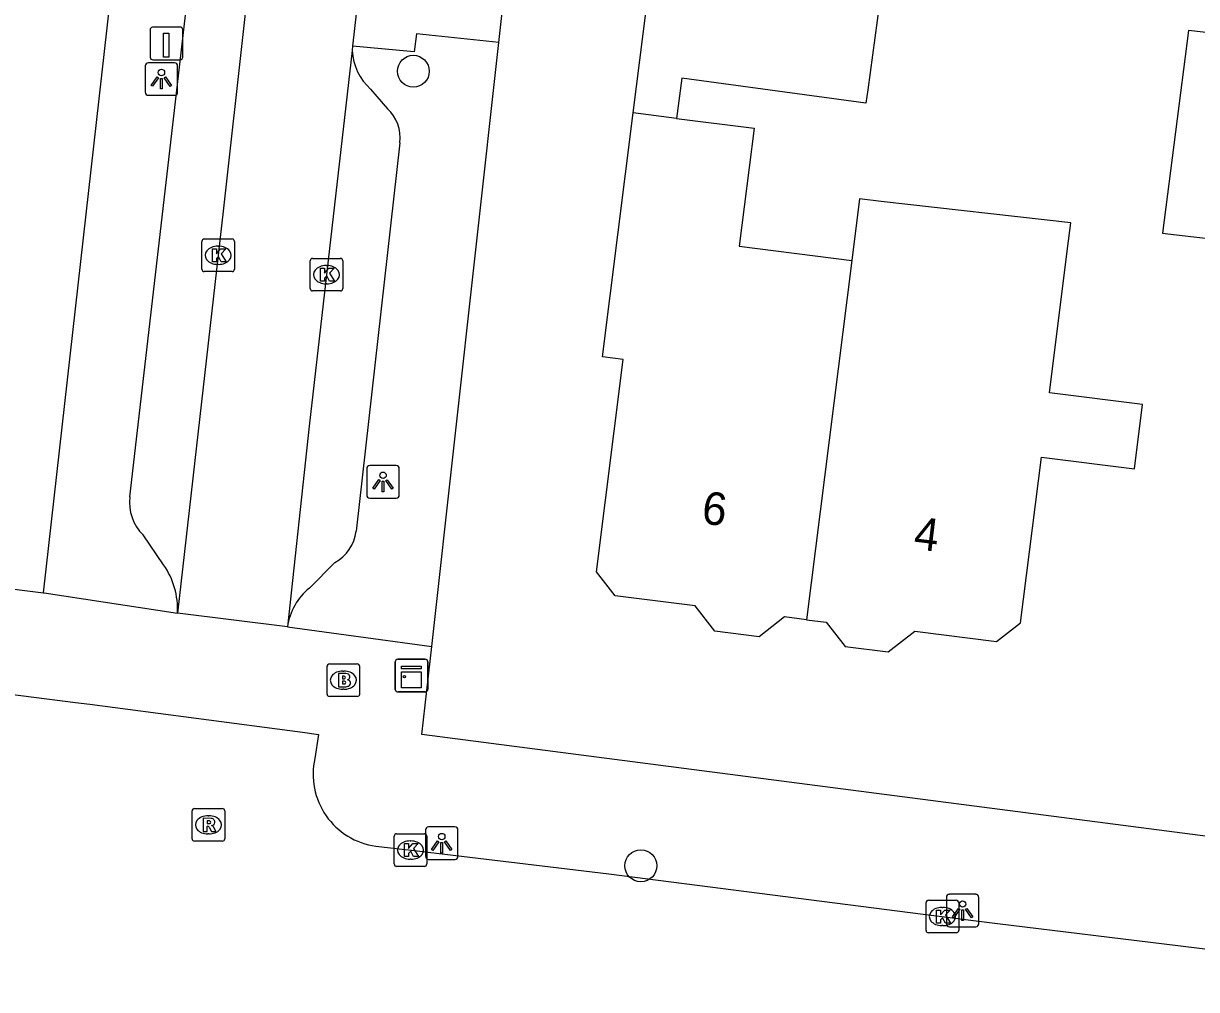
# Model space of a CAD drawing. Extents: x 161258 to 161838, y 380836 to 381727.
# Drawn here: x 161699.94 to 161735.93, y 381339.67 to 381369.3 of the extents above; entities that cross this region are included whole.
import ezdxf

# ---------------------------------------------------------------- set-up
doc = ezdxf.new("R2010")
doc.units = 0
for name, color, linetype in [('IMGEO_Boom', 7, 'Continuous'), ('IMGEO_Brandkraan', 7, 'Continuous'), ('IMGEO_Kast', 7, 'Continuous'), ('IMGEO_Kolk', 7, 'Continuous'), ('IMGEO_Laadpaal', 7, 'Continuous'), ('IMGEO_Lichtpunt', 7, 'Continuous'), ('IMGEO_Pand', 7, 'Continuous'), ('IMGEO_Pand_nummerreeks', 7, 'Continuous'), ('IMGEO_Rijbaan_lokaal_open', 7, 'Continuous'), ('IMGEO_Rioolput', 7, 'Continuous'), ('IMGEO_Voetpad_open', 7, 'Continuous')]:
    doc.layers.add(name, color=color, linetype=linetype)

msp = doc.modelspace()

# ---------------------------------------------------------------- linework, layer by layer
at = {"layer": 'IMGEO_Boom'}
for centre in [(161711.901, 381367.833), (161718.88, 381343.465)]:
    msp.add_circle(centre, 0.489, dxfattribs=at)
at = {"layer": 'IMGEO_Brandkraan'}
for p, q in [((161709.252, 381348.731), (161709.252, 381349.583)), ((161709.327, 381349.657), (161710.179, 381349.657)), ((161710.253, 381349.583), (161710.253, 381348.731)), ((161709.74, 381349.437), (161709.765, 381349.437)), ((161709.763, 381348.877), (161709.738, 381348.877)), ((161710.179, 381348.657), (161709.327, 381348.657))]:
    msp.add_line(p, q, dxfattribs=at)
for points in [[(161709.252, 381348.731), (161709.252, 381349.583)], [(161709.327, 381349.657), (161710.179, 381349.657)], [(161710.253, 381349.583), (161710.253, 381348.731)], [(161709.6, 381349.357), (161709.6, 381348.957), (161709.813, 381348.957)], [(161709.831, 381349.357), (161709.6, 381349.357)], [(161709.779, 381349.276), (161709.725, 381349.276), (161709.725, 381349.2)], [(161709.725, 381349.2), (161709.778, 381349.2)], [(161709.787, 381349.124), (161709.725, 381349.124), (161709.725, 381349.043)], [(161709.725, 381349.043), (161709.787, 381349.043)], [(161710.179, 381348.657), (161709.327, 381348.657)]]:
    msp.add_lwpolyline(points, dxfattribs=at)
for centre, radius, start, end in [((161709.329, 381349.581), 0.0765, 91.552, 178.448), ((161709.329, 381349.581), 0.0765, 91.552, 178.448), ((161710.177, 381349.581), 0.0765, 1.552, 88.448), ((161710.177, 381349.581), 0.0765, 1.552, 88.448), ((161709.78, 381349.238), 0.0379, 267.8285, 90.9355), ((161709.835, 381349.212), 0.145, 59.4692, 91.5367), ((161709.86, 381349.259), 0.0922, 285.5137, 58.1501), ((161709.788, 381349.083), 0.0404, 269.8759, 90.5077), ((161709.819, 381349.208), 0.251, 268.6676, 293.5347), ((161709.865, 381349.067), 0.105, 301.3115, 78.989), ((161709.329, 381348.733), 0.0765, 181.552, 268.448), ((161709.329, 381348.733), 0.0765, 181.552, 268.448), ((161710.177, 381348.733), 0.0765, 271.552, 358.448), ((161710.177, 381348.733), 0.0765, 271.552, 358.448)]:
    msp.add_arc(centre, radius, start, end, dxfattribs=at)
for centre, major_axis, ratio, start_param, end_param in [((161709.739, 381349.157), (-0.387, 0.002), 0.722429, 4.712389, 7.853982), ((161709.764, 381349.157), (-0.39, 0.002), 0.717154, 1.570796, 4.712389)]:
    msp.add_ellipse(centre, major_axis=major_axis, ratio=ratio, start_param=start_param, end_param=end_param, dxfattribs=at)
at = {"layer": 'IMGEO_Kast'}
for p, q in [((161711.346, 381348.874), (161711.346, 381349.715)), ((161711.346, 381349.715), (161711.346, 381348.874)), ((161711.421, 381349.799), (161712.262, 381349.799)), ((161712.262, 381349.799), (161711.421, 381349.799)), ((161712.346, 381349.724), (161712.346, 381348.883)), ((161712.346, 381348.883), (161712.346, 381349.724)), ((161712.271, 381348.799), (161711.43, 381348.799)), ((161711.43, 381348.799), (161712.271, 381348.799))]:
    msp.add_line(p, q, dxfattribs=at)
for points in [[(161711.541, 381349.589), (161712.141, 381349.589), (161712.141, 381349.504), (161711.541, 381349.504), (161711.541, 381349.589)], [(161711.541, 381349.414), (161712.141, 381349.414), (161712.141, 381348.925), (161711.541, 381348.925), (161711.541, 381349.414)]]:
    msp.add_lwpolyline(points, dxfattribs=at)
msp.add_circle((161711.625, 381349.263), 0.0377, dxfattribs=at)
for centre, start, end in [((161711.424, 381349.721), 92.4484, 184.2845), ((161711.424, 381349.721), 92.4484, 184.2845), ((161712.268, 381349.721), 2.4484, 94.2845), ((161712.268, 381349.721), 2.4484, 94.2845), ((161711.424, 381348.877), 182.4484, 274.2845), ((161711.424, 381348.877), 182.4484, 274.2845), ((161712.268, 381348.877), 272.4484, 4.2845), ((161712.268, 381348.877), 272.4484, 4.2845)]:
    msp.add_arc(centre, 0.0779, start, end, dxfattribs=at)
at = {"layer": 'IMGEO_Kolk'}
for p, q in [((161705.412, 381361.763), (161705.412, 381362.615)), ((161705.487, 381362.689), (161706.339, 381362.689)), ((161706.413, 381362.615), (161706.413, 381361.763)), ((161705.9, 381362.469), (161705.925, 381362.469)), ((161705.923, 381361.909), (161705.898, 381361.909)), ((161708.734, 381361.169), (161708.734, 381362.021)), ((161708.809, 381362.095), (161709.661, 381362.095)), ((161709.222, 381361.875), (161709.247, 381361.875)), ((161709.735, 381362.021), (161709.735, 381361.169)), ((161706.339, 381361.689), (161705.487, 381361.689)), ((161709.661, 381361.095), (161708.809, 381361.095)), ((161709.245, 381361.315), (161709.22, 381361.315)), ((161711.312, 381343.52), (161711.312, 381344.372)), ((161711.387, 381344.446), (161712.239, 381344.446)), ((161711.8, 381344.226), (161711.825, 381344.226)), ((161712.313, 381344.372), (161712.313, 381343.52)), ((161712.239, 381343.446), (161711.387, 381343.446)), ((161711.823, 381343.666), (161711.798, 381343.666)), ((161727.707, 381342.408), (161728.559, 381342.408)), ((161727.632, 381341.482), (161727.632, 381342.334)), ((161728.12, 381342.188), (161728.145, 381342.188)), ((161728.633, 381342.334), (161728.633, 381341.482)), ((161728.559, 381341.408), (161727.707, 381341.408)), ((161728.143, 381341.628), (161728.118, 381341.628))]:
    msp.add_line(p, q, dxfattribs=at)
for points in [[(161705.412, 381361.763), (161705.412, 381362.615)], [(161705.487, 381362.689), (161706.339, 381362.689)], [(161706.413, 381362.615), (161706.413, 381361.763)], [(161705.733, 381362.389), (161705.856, 381362.389), (161705.856, 381362.238), (161705.986, 381362.389), (161706.15, 381362.389), (161706.004, 381362.238), (161706.157, 381361.989), (161706.005, 381361.989), (161705.92, 381362.153), (161705.856, 381362.086), (161705.856, 381361.989), (161705.733, 381361.989), (161705.733, 381362.389)], [(161708.734, 381361.169), (161708.734, 381362.021)], [(161708.809, 381362.095), (161709.661, 381362.095)], [(161709.055, 381361.795), (161709.178, 381361.795), (161709.178, 381361.644), (161709.308, 381361.795), (161709.472, 381361.795), (161709.326, 381361.644), (161709.479, 381361.395), (161709.327, 381361.395), (161709.242, 381361.559), (161709.178, 381361.492), (161709.178, 381361.395), (161709.055, 381361.395), (161709.055, 381361.795)], [(161709.735, 381362.021), (161709.735, 381361.169)], [(161706.339, 381361.689), (161705.487, 381361.689)], [(161709.661, 381361.095), (161708.809, 381361.095)], [(161711.312, 381343.52), (161711.312, 381344.372)], [(161711.387, 381344.446), (161712.239, 381344.446)], [(161712.313, 381344.372), (161712.313, 381343.52)], [(161711.633, 381344.146), (161711.756, 381344.146), (161711.756, 381343.995), (161711.886, 381344.146), (161712.05, 381344.146), (161711.904, 381343.995), (161712.057, 381343.746), (161711.905, 381343.746), (161711.82, 381343.91), (161711.756, 381343.843), (161711.756, 381343.746), (161711.633, 381343.746), (161711.633, 381344.146)], [(161712.239, 381343.446), (161711.387, 381343.446)], [(161727.707, 381342.408), (161728.559, 381342.408)], [(161727.632, 381341.482), (161727.632, 381342.334)], [(161727.953, 381342.108), (161728.076, 381342.108), (161728.076, 381341.957), (161728.206, 381342.108), (161728.37, 381342.108), (161728.224, 381341.957), (161728.377, 381341.708), (161728.225, 381341.708), (161728.14, 381341.872), (161728.076, 381341.805), (161728.076, 381341.708), (161727.953, 381341.708), (161727.953, 381342.108)], [(161728.633, 381342.334), (161728.633, 381341.482)], [(161728.559, 381341.408), (161727.707, 381341.408)]]:
    msp.add_lwpolyline(points, dxfattribs=at)
for centre, start, end in [((161705.489, 381362.613), 91.552, 178.448), ((161705.489, 381362.613), 91.552, 178.448), ((161706.337, 381362.613), 1.552, 88.448), ((161706.337, 381362.613), 1.552, 88.448), ((161708.811, 381362.019), 91.552, 178.448), ((161708.811, 381362.019), 91.552, 178.448), ((161709.659, 381362.019), 1.552, 88.448), ((161709.659, 381362.019), 1.552, 88.448), ((161705.489, 381361.765), 181.552, 268.448), ((161705.489, 381361.765), 181.552, 268.448), ((161706.337, 381361.765), 271.552, 358.448), ((161706.337, 381361.765), 271.552, 358.448), ((161708.811, 381361.171), 181.552, 268.448), ((161708.811, 381361.171), 181.552, 268.448), ((161709.659, 381361.171), 271.552, 358.448), ((161709.659, 381361.171), 271.552, 358.448), ((161711.389, 381344.37), 91.552, 178.448), ((161711.389, 381344.37), 91.552, 178.448), ((161712.237, 381344.37), 1.552, 88.448), ((161712.237, 381344.37), 1.552, 88.448), ((161711.389, 381343.522), 181.552, 268.448), ((161711.389, 381343.522), 181.552, 268.448), ((161712.237, 381343.522), 271.552, 358.448), ((161712.237, 381343.522), 271.552, 358.448), ((161727.709, 381342.332), 91.552, 178.448), ((161727.709, 381342.332), 91.552, 178.448), ((161728.557, 381342.332), 1.552, 88.448), ((161728.557, 381342.332), 1.552, 88.448), ((161727.709, 381341.484), 181.552, 268.448), ((161727.709, 381341.484), 181.552, 268.448), ((161728.557, 381341.484), 271.552, 358.448), ((161728.557, 381341.484), 271.552, 358.448)]:
    msp.add_arc(centre, 0.0765, start, end, dxfattribs=at)
for centre, major_axis, ratio, start_param, end_param in [((161705.899, 381362.189), (-0.387, 0.002), 0.722429, 4.712389, 7.853982), ((161705.924, 381362.189), (-0.39, 0.002), 0.717154, 1.570796, 4.712389), ((161709.221, 381361.595), (-0.387, 0.002), 0.722429, 4.712389, 7.853982), ((161709.246, 381361.595), (-0.39, 0.002), 0.717154, 1.570796, 4.712389), ((161711.799, 381343.946), (-0.387, 0.002), 0.722429, 4.712389, 7.853982), ((161711.824, 381343.946), (-0.39, 0.002), 0.717154, 1.570796, 4.712389), ((161728.119, 381341.908), (-0.387, 0.002), 0.722429, 4.712389, 7.853982), ((161728.144, 381341.908), (-0.39, 0.002), 0.717154, 1.570796, 4.712389)]:
    msp.add_ellipse(centre, major_axis=major_axis, ratio=ratio, start_param=start_param, end_param=end_param, dxfattribs=at)
at = {"layer": 'IMGEO_Laadpaal'}
for p, q in [((161703.823, 381369.102), (161703.823, 381368.261)), ((161703.823, 381369.102), (161703.823, 381368.261)), ((161704.739, 381369.186), (161703.898, 381369.186)), ((161704.739, 381369.186), (161703.898, 381369.186)), ((161704.823, 381368.27), (161704.823, 381369.111)), ((161704.823, 381368.27), (161704.823, 381369.111)), ((161703.907, 381368.186), (161704.748, 381368.186)), ((161703.907, 381368.186), (161704.748, 381368.186))]:
    msp.add_line(p, q, dxfattribs=at)
msp.add_lwpolyline([(161704.238, 381368.999), (161704.398, 381368.999), (161704.398, 381368.266), (161704.238, 381368.266), (161704.238, 381368.999)], dxfattribs=at)
for centre, start, end in [((161703.901, 381369.108), 92.4484, 184.2845), ((161703.901, 381369.108), 92.4484, 184.2845), ((161704.745, 381369.108), 2.4484, 94.2845), ((161704.745, 381369.108), 2.4484, 94.2845), ((161704.745, 381368.264), 272.4484, 4.2845), ((161704.745, 381368.264), 272.4484, 4.2845), ((161703.901, 381368.264), 182.4484, 274.2845), ((161703.901, 381368.264), 182.4484, 274.2845)]:
    msp.add_arc(centre, 0.0779, start, end, dxfattribs=at)
at = {"layer": 'IMGEO_Lichtpunt'}
for p, q in [((161703.671, 381367.997), (161703.671, 381367.19)), ((161703.671, 381367.997), (161703.671, 381367.19)), ((161704.573, 381368.092), (161703.765, 381368.092)), ((161704.573, 381368.092), (161703.765, 381368.092)), ((161704.667, 381367.19), (161704.667, 381367.997)), ((161704.667, 381367.19), (161704.667, 381367.997)), ((161703.765, 381367.096), (161704.573, 381367.096)), ((161703.765, 381367.096), (161704.573, 381367.096)), ((161711.373, 381355.738), (161710.565, 381355.738)), ((161711.373, 381355.738), (161710.565, 381355.738)), ((161710.471, 381355.643), (161710.471, 381354.836)), ((161710.471, 381355.643), (161710.471, 381354.836)), ((161711.467, 381354.836), (161711.467, 381355.643)), ((161711.467, 381354.836), (161711.467, 381355.643)), ((161710.565, 381354.742), (161711.373, 381354.742)), ((161710.565, 381354.742), (161711.373, 381354.742)), ((161712.272, 381344.562), (161712.272, 381343.755)), ((161712.272, 381344.562), (161712.272, 381343.755)), ((161713.174, 381344.657), (161712.366, 381344.657)), ((161713.174, 381344.657), (161712.366, 381344.657)), ((161713.268, 381343.755), (161713.268, 381344.562)), ((161713.268, 381343.755), (161713.268, 381344.562)), ((161712.366, 381343.661), (161713.174, 381343.661)), ((161712.366, 381343.661), (161713.174, 381343.661)), ((161728.256, 381342.494), (161728.256, 381341.687)), ((161728.256, 381342.494), (161728.256, 381341.687)), ((161729.158, 381342.589), (161728.35, 381342.589)), ((161729.158, 381342.589), (161728.35, 381342.589)), ((161729.252, 381341.687), (161729.252, 381342.494)), ((161729.252, 381341.687), (161729.252, 381342.494)), ((161728.35, 381341.593), (161729.158, 381341.593)), ((161728.35, 381341.593), (161729.158, 381341.593))]:
    msp.add_line(p, q, dxfattribs=at)
for points in [[(161704.045, 381367.661), (161704.084, 381367.633), (161703.896, 381367.371), (161703.858, 381367.398), (161704.045, 381367.661)], [(161704.147, 381367.613), (161704.194, 381367.613), (161704.194, 381367.291), (161704.147, 381367.291), (161704.147, 381367.613)], [(161704.257, 381367.633), (161704.295, 381367.66), (161704.482, 381367.398), (161704.443, 381367.37), (161704.257, 381367.633)], [(161710.845, 381355.307), (161710.884, 381355.279), (161710.696, 381355.017), (161710.658, 381355.044), (161710.845, 381355.307)], [(161710.947, 381355.259), (161710.994, 381355.259), (161710.994, 381354.937), (161710.947, 381354.937), (161710.947, 381355.259)], [(161711.057, 381355.279), (161711.095, 381355.306), (161711.282, 381355.044), (161711.243, 381355.016), (161711.057, 381355.279)], [(161712.646, 381344.226), (161712.685, 381344.198), (161712.497, 381343.936), (161712.459, 381343.963), (161712.646, 381344.226)], [(161712.748, 381344.178), (161712.795, 381344.178), (161712.795, 381343.856), (161712.748, 381343.856), (161712.748, 381344.178)], [(161712.858, 381344.198), (161712.896, 381344.225), (161713.083, 381343.963), (161713.044, 381343.935), (161712.858, 381344.198)], [(161728.63, 381342.158), (161728.669, 381342.13), (161728.481, 381341.868), (161728.443, 381341.895), (161728.63, 381342.158)], [(161728.732, 381342.11), (161728.779, 381342.11), (161728.779, 381341.788), (161728.732, 381341.788), (161728.732, 381342.11)], [(161728.842, 381342.13), (161728.88, 381342.157), (161729.067, 381341.895), (161729.028, 381341.867), (161728.842, 381342.13)]]:
    msp.add_lwpolyline(points, dxfattribs=at)
for centre in [(161704.17, 381367.795), (161710.97, 381355.441), (161712.771, 381344.36), (161728.755, 381342.292)]:
    msp.add_circle(centre, 0.0994, dxfattribs=at)
for centre, start, end in [((161703.765, 381367.997), 90, 180), ((161703.765, 381367.997), 90, 180), ((161704.573, 381367.997), 0, 90), ((161704.573, 381367.997), 0, 90), ((161703.765, 381367.19), 180, 270), ((161703.765, 381367.19), 180, 270), ((161704.573, 381367.19), 270, 0), ((161704.573, 381367.19), 270, 360), ((161710.565, 381355.643), 90, 180), ((161710.565, 381355.643), 90, 180), ((161711.373, 381355.643), 0, 90), ((161711.373, 381355.643), 0, 90), ((161710.565, 381354.836), 180, 270), ((161710.565, 381354.836), 180, 270), ((161711.373, 381354.836), 270, 0), ((161711.373, 381354.836), 270, 360), ((161712.366, 381344.562), 90, 180), ((161712.366, 381344.562), 90, 180), ((161713.174, 381344.562), 0, 90), ((161713.174, 381344.562), 0, 90), ((161712.366, 381343.755), 180, 270), ((161712.366, 381343.755), 180, 270), ((161713.174, 381343.755), 270, 0), ((161713.174, 381343.755), 270, 360), ((161728.35, 381342.494), 90, 180), ((161728.35, 381342.494), 90, 180), ((161729.158, 381342.494), 0, 90), ((161729.158, 381342.494), 0, 90), ((161728.35, 381341.687), 180, 270), ((161728.35, 381341.687), 180, 270), ((161729.158, 381341.687), 270, 0), ((161729.158, 381341.687), 270, 360)]:
    msp.add_arc(centre, 0.0946, start, end, dxfattribs=at)
at = {"layer": 'IMGEO_Pand'}
for points in [[(161718.648, 381366.553), (161719.259, 381371.413), (161719.984, 381371.315), (161726.277, 381370.462), (161725.843, 381367.261), (161725.788, 381366.858), (161720.142, 381367.623), (161719.975, 381366.387)], [(161740.464, 381368.537), (161735.68, 381369.079), (161734.89, 381362.864), (161735.049, 381362.846), (161738.149, 381362.494)], [(161723.964, 381351.013), (161723.291, 381351.098), (161722.507, 381350.489), (161721.151, 381350.659), (161720.549, 381351.434), (161718.092, 381351.742), (161717.52, 381352.479), (161718.337, 381358.995), (161717.708, 381359.073), (161718.648, 381366.553)], [(161719.975, 381366.387), (161718.648, 381366.553)], [(161719.975, 381366.387), (161722.356, 381366.088), (161721.901, 381362.467), (161725.35, 381362.034)], [(161723.964, 381351.013), (161724.571, 381350.937), (161725.151, 381350.19), (161726.469, 381350.025), (161727.283, 381350.657), (161729.798, 381350.341), (161730.534, 381350.913), (161731.172, 381356.001), (161734.027, 381355.642), (161734.274, 381357.615), (161731.419, 381357.973), (161731.974, 381362.395), (161732.073, 381363.183), (161726.251, 381363.842), (161725.587, 381363.918), (161725.35, 381362.034)], [(161725.35, 381362.034), (161723.964, 381351.013)]]:
    msp.add_lwpolyline(points, dxfattribs=at)
at = {"layer": 'IMGEO_Rijbaan_lokaal_open'}
for points in [[(161707.343, 381375.038), (161706.079, 381363.637), (161704.663, 381351.215)], [(161710.748, 381374.936), (161710.037, 381368.604)], [(161710.022, 381368.469), (161708.701, 381356.944), (161708.039, 381350.79)], [(161710.037, 381368.604), (161710.022, 381368.469)], [(161708.039, 381350.79), (161704.663, 381351.215)], [(161696.089, 381349.172), (161701.538, 381348.474), (161701.97, 381348.417), (161708.497, 381347.56), (161708.995, 381347.495), (161708.88, 381346.759)], [(161710.75, 381344.069), (161711.557, 381343.975), (161711.839, 381343.942), (161717.901, 381343.221), (161727.547, 381341.978), (161729.822, 381341.699), (161735.362, 381341.02), (161739.43, 381340.521), (161745.88, 381339.669)]]:
    msp.add_lwpolyline(points, dxfattribs=at)
msp.add_arc((161711.044, 381346.268), 2.219, 167.229, 262.3825, dxfattribs=at)
at = {"layer": 'IMGEO_Rioolput'}
for p, q in [((161705.112, 381344.294), (161705.112, 381345.146)), ((161705.187, 381345.22), (161706.039, 381345.22)), ((161705.6, 381345), (161705.625, 381345)), ((161706.113, 381345.146), (161706.113, 381344.294)), ((161706.039, 381344.22), (161705.187, 381344.22)), ((161705.623, 381344.44), (161705.598, 381344.44))]:
    msp.add_line(p, q, dxfattribs=at)
for points in [[(161705.112, 381344.294), (161705.112, 381345.146)], [(161705.187, 381345.22), (161706.039, 381345.22)], [(161705.701, 381344.918), (161705.449, 381344.92), (161705.449, 381344.52)], [(161706.113, 381345.146), (161706.113, 381344.294)], [(161705.449, 381344.52), (161705.573, 381344.52), (161705.573, 381344.682), (161705.584, 381344.682)], [(161705.627, 381344.839), (161705.573, 381344.839), (161705.573, 381344.758)], [(161705.573, 381344.758), (161705.625, 381344.758)], [(161705.631, 381344.653), (161705.702, 381344.52), (161705.842, 381344.52), (161705.777, 381344.646)], [(161706.039, 381344.22), (161705.187, 381344.22)]]:
    msp.add_lwpolyline(points, dxfattribs=at)
for centre, radius, start, end in [((161705.189, 381345.144), 0.0765, 91.552, 178.448), ((161705.189, 381345.144), 0.0765, 91.552, 178.448), ((161705.7, 381344.808), 0.109, 350.3612, 89.416), ((161706.037, 381345.144), 0.0765, 1.552, 88.448), ((161706.037, 381345.144), 0.0765, 1.552, 88.448), ((161705.583, 381344.629), 0.0533, 26.0293, 88.6989), ((161705.609, 381344.947), 0.19, 274.7715, 282.9687), ((161705.633, 381344.743), 0.0964, 77.0061, 93.1865), ((161705.647, 381344.8), 0.0378, 276.6634, 79.6772), ((161705.698, 381344.808), 0.112, 277.5842, 350.9817), ((161705.682, 381344.593), 0.108, 29.5134, 73.7905), ((161705.189, 381344.296), 0.0765, 181.552, 268.448), ((161705.189, 381344.296), 0.0765, 181.552, 268.448), ((161706.037, 381344.296), 0.0765, 271.552, 358.448), ((161706.037, 381344.296), 0.0765, 271.552, 358.448)]:
    msp.add_arc(centre, radius, start, end, dxfattribs=at)
for centre, major_axis, ratio, start_param, end_param in [((161705.599, 381344.72), (-0.387, 0.002), 0.722429, 4.712389, 7.853982), ((161705.624, 381344.72), (-0.39, 0.002), 0.717154, 1.570796, 4.712389)]:
    msp.add_ellipse(centre, major_axis=major_axis, ratio=ratio, start_param=start_param, end_param=end_param, dxfattribs=at)
at = {"layer": 'IMGEO_Voetpad_open'}
for points in [[(161700.55, 381351.841), (161703.323, 381376.439)], [(161714.528, 381368.72), (161715.1, 381373.857)], [(161703.205, 381354.779), (161705.2, 381372.037)], [(161714.528, 381368.72), (161711.992, 381368.979), (161711.926, 381368.434), (161710.037, 381368.604)], [(161712.463, 381350.189), (161714.528, 381368.72)], [(161710.589, 381367.283), (161711.107, 381366.685)], [(161711.484, 381365.642), (161710.144, 381353.727)], [(161704.237, 381352.694), (161703.606, 381353.61)], [(161689.572, 381353.221), (161700.55, 381351.841)], [(161709.493, 381352.764), (161708.715, 381351.98)], [(161700.55, 381351.841), (161700.57, 381351.838), (161704.663, 381351.215)], [(161708.039, 381350.79), (161712.463, 381350.189)], [(161746.295, 381343.062), (161712.163, 381347.496), (161712.463, 381350.189)]]:
    msp.add_lwpolyline(points, dxfattribs=at)
for centre, radius, start, end in [((161711.755, 381368.569), 1.736, 183.3, 227.8028), ((161710.309, 381365.807), 1.186, 352.0017, 47.7438), ((161704.578, 381354.597), 1.385, 172.4388, 225.428), ((161708.891, 381353.873), 1.261, 298.5061, 353.3756), ((161702.289, 381351.332), 2.377, 357.1783, 34.958), ((161709.871, 381350.536), 1.85, 128.6889, 172.1122)]:
    msp.add_arc(centre, radius, start, end, dxfattribs=at)

# ---------------------------------------------------------------- texts
at = {"layer": 'IMGEO_Pand_nummerreeks'}
for s, p in [('6', (161720.719, 381353.967)), ('4', (161727.226, 381353.184))]:
    msp.add_text(s, height=1, rotation=353.1417, dxfattribs=at).set_placement(p)

doc.saveas('drawing.dxf')
